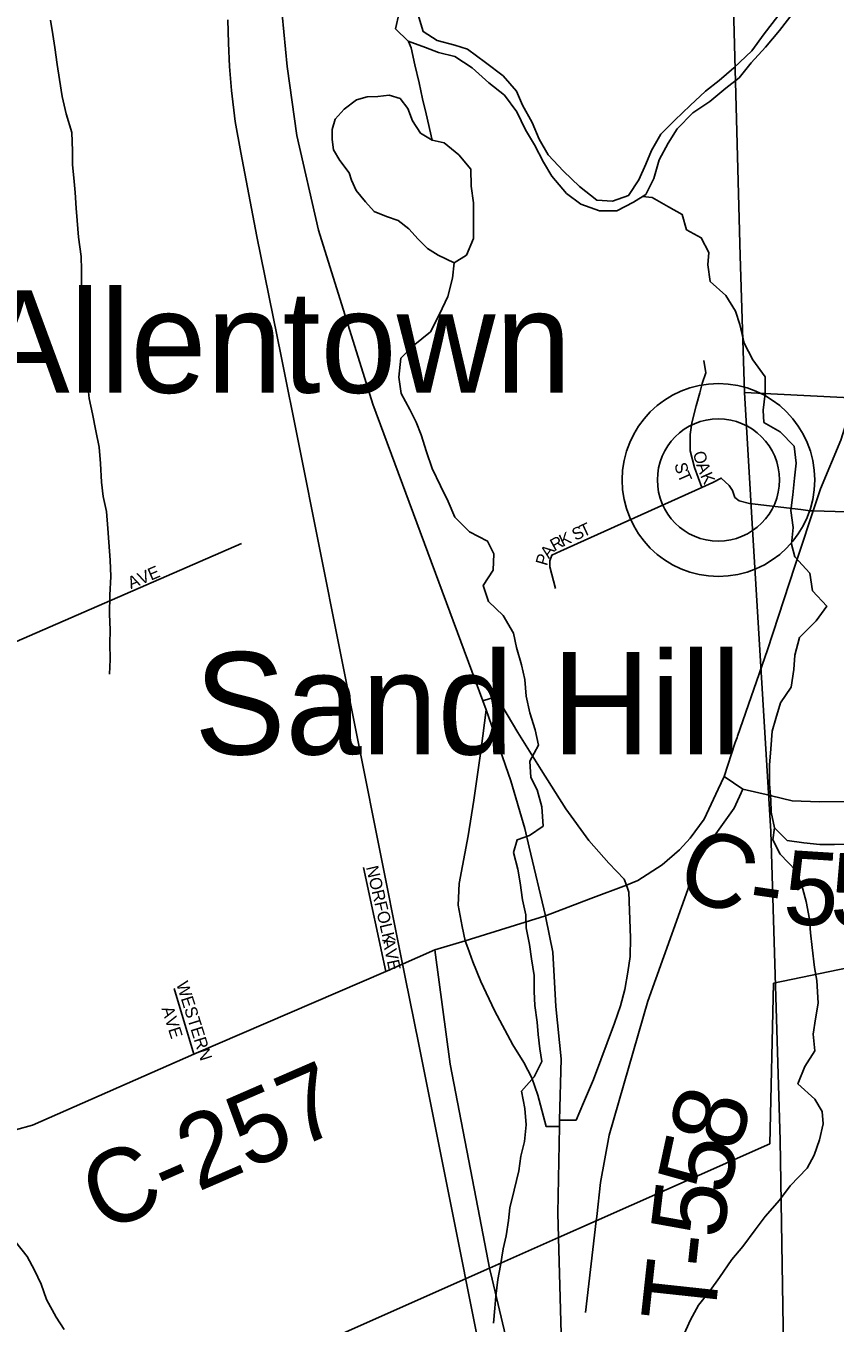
# Model space of a CAD drawing. Extents: x 1624196 to 2029251, y 146837 to 440034.
# Drawn here: x 1863402 to 1866701, y 250304 to 255591 of the extents above; entities that cross this region are included whole.
import ezdxf

# ---------------------------------------------------------------- set-up
doc = ezdxf.new("R2010")
doc.units = 0
for name, color, linetype in [('GM_X_County_Road', 7, 'Continuous'), ('GM_X_County_Road_Text', 7, 'Continuous'), ('GM_X_Interchange_Ramps', 7, 'Continuous'), ('GM_X_Minor_Lake', 7, 'Continuous'), ('GM_X_Minor_River', 7, 'Continuous'), ('GM_X_Rail_Line', 7, 'Continuous'), ('GM_X_Section', 7, 'Continuous'), ('GM_X_State_Route', 7, 'Continuous'), ('GM_X_Township', 7, 'Continuous'), ('GM_X_Township_Road', 7, 'Continuous'), ('GM_X_Township_Road_Text', 7, 'Continuous'), ('GM_X_Township_Subdivision', 7, 'Continuous'), ('GM_X_Township_Subdivision_Text', 7, 'Continuous'), ('GM_X_Unincorporated', 7, 'Continuous'), ('GM_X_Unincorporated_Location', 7, 'Continuous'), ('GM_X_Unincorporated_Text', 7, 'Continuous'), ('GM_X_US_Route', 7, 'Continuous')]:
    doc.layers.add(name, color=color, linetype=linetype)

msp = doc.modelspace()

# ---------------------------------------------------------------- linework, layer by layer
at = {"layer": 'GM_X_County_Road'}
for points in [[(1865193.3, 251862.7), (1865069.6, 251825.3), (1864868.7, 251736.8), (1864086.7, 251400.9), (1863428.9, 251110.7), (1863359.5, 251091.4), (1863284.9, 251085), (1863251.9, 251085.8), (1863225.8, 251096.5), (1863173.1, 251132.6), (1863116.5, 251177.6), (1863066.4, 251234.1), (1862399.8, 252003.8), (1862350.4, 252078.3), (1862310.9, 252140.7), (1862275.6, 252233.1), (1862160.4, 252559.1), (1861891.5, 253320.6), (1861889.7, 253325.6), (1861870.2, 253389.9), (1861867.9, 253405.1)], [(1866249.4, 252532.3), (1866325.2, 252480.5), (1866437.9, 252454.6), (1866441.7, 252453.7)], [(1866441.7, 252453.7), (1866526.7, 252432.4), (1866637.6, 252428.8), (1866776.3, 252430.6), (1866877.9, 252426.9), (1867020.3, 252421.3)]]:
    msp.add_lwpolyline(points, dxfattribs=at)
at = {"layer": 'GM_X_Interchange_Ramps'}
for points in [[(1865850.3, 252089), (1865841.8, 252114), (1865778.6, 252178.6), (1865696.7, 252271.7), (1865603.5, 252400.3), (1865502.9, 252558.7), (1865407.9, 252711.5), (1865320.3, 252858.6), (1865265, 252840.8)], [(1865577.4, 251131.8), (1865645.4, 251131.1), (1865675.2, 251202.1), (1865715.8, 251297), (1865802.4, 251526.5), (1865826.7, 251596.9), (1865843.9, 251664.5), (1865856.7, 251734.9), (1865865.9, 251798.2), (1865867.3, 251873.8), (1865859.7, 252061), (1865850.3, 252089)], [(1865193.3, 251862.7), (1865203.1, 251833.5), (1865224.4, 251777.2), (1865256.1, 251696), (1865312.4, 251578.1), (1865387.4, 251438.7), (1865432.5, 251366.8), (1865465.3, 251303.8), (1865489.5, 251233.7), (1865523.2, 251105.5), (1865577.1, 251104.9)]]:
    msp.add_lwpolyline(points, dxfattribs=at)
at = {"layer": 'GM_X_Minor_Lake'}
for points in [[(1865057.9, 255125.9), (1865010.2, 255154.3), (1864978.5, 255204.5), (1864958.8, 255254.7), (1864927.1, 255294.9), (1864883.2, 255309.2), (1864837.3, 255303.5), (1864793.3, 255301.8), (1864749.2, 255290), (1864699, 255252.3), (1864662.8, 255210.5), (1864650.5, 255168.5), (1864650.3, 255128.5), (1864656, 255086.4), (1864681.7, 255042.2), (1864719.4, 254991.9), (1864729.2, 254961.8), (1864748.9, 254919.7), (1864786.6, 254873.4), (1864822.3, 254835.1), (1864872.1, 254814.8), (1864920, 254798.5), (1864963.7, 254764.2), (1865001.4, 254721.9), (1865039.2, 254683.6), (1865082.9, 254657.3), (1865147.4, 254625.7)], [(1865147.4, 254625.7), (1865197.7, 254657.3), (1865226.2, 254725.2), (1865227.3, 254869.4), (1865217.9, 254937.5), (1865216.4, 255007.6), (1865166.9, 255066.1), (1865107.4, 255114.6), (1865057.9, 255125.9)]]:
    msp.add_lwpolyline(points, dxfattribs=at)
at = {"layer": 'GM_X_Minor_River'}
for points in [[(1863502.5, 255613.8), (1863512, 255555.7), (1863519.6, 255503.5), (1863529, 255433.4), (1863538.5, 255373.2), (1863550, 255303.1), (1863565.4, 255232.9), (1863588.8, 255156.6), (1863592.2, 255082.5), (1863591.7, 255024.4), (1863597.3, 254972.3), (1863602.8, 254912.1), (1863606.3, 254848), (1863609.9, 254798), (1863615.4, 254729.8), (1863626.7, 254651.6), (1863628.3, 254597.5), (1863627.8, 254537.5), (1863625.3, 254473.4), (1863628.7, 254399.3), (1863634.2, 254335.2), (1863639.8, 254279), (1863643.1, 254196.9), (1863652.7, 254140.8), (1863660.1, 254072.6), (1863673.6, 254010.4), (1863687, 253940.2), (1863700.5, 253874), (1863706, 253807.9), (1863709.4, 253731.8), (1863716.9, 253673.6), (1863730.4, 253611.4), (1863735.9, 253543.3), (1863739.4, 253487.2)], [(1864923.7, 255644.7), (1864909.2, 255578.7), (1864960.7, 255528.3), (1865030.5, 255503.7), (1865084.3, 255483.2), (1865150.1, 255466.7), (1865221.7, 255420.1), (1865289.2, 255359.5), (1865352.7, 255308.9), (1865404.1, 255240.4), (1865439.5, 255168), (1865475, 255105.7), (1865512.4, 255035.3), (1865546, 254979), (1865605.4, 254908.4), (1865665, 254863.9), (1865740.7, 254837.3), (1865810.7, 254836.7), (1865878.9, 254872.2), (1865929.1, 254903.9), (1865961.6, 254969.7), (1865984.2, 255045.6), (1866020.7, 255113.4), (1866057.1, 255171.2), (1866121.6, 255236.8), (1866189.9, 255282.3), (1866256.3, 255337.9), (1866310.6, 255379.5), (1866359, 255441.2), (1866417.5, 255504.8), (1866474, 255572.4), (1866530.5, 255644.1)], [(1866468.5, 255630.5), (1866411.9, 255558.9), (1866361.4, 255489.2), (1866288.9, 255419.7), (1866228.6, 255368.1), (1866172.3, 255324.5), (1866109.8, 255266.9), (1866047.4, 255207.3), (1865991, 255149.7), (1865952.5, 255083.9), (1865930.1, 255028), (1865901.6, 254964.2), (1865859.1, 254900.4), (1865793, 254876.9), (1865729.1, 254881.4), (1865659.5, 254936), (1865594.1, 254998.6), (1865530.7, 255065.2), (1865495.2, 255129.6), (1865465.8, 255197.9), (1865426.3, 255268.3), (1865402.8, 255324.5), (1865347.3, 255387), (1865275.8, 255441.7), (1865202.3, 255496.3), (1865150.5, 255512.8), (1865078.7, 255531.3), (1865021, 255567.8), (1864999.6, 255640.1)], [(1864961.9, 255527.9), (1864972.5, 255502.1), (1864988, 255431.9), (1865005.4, 255359.7), (1865018.8, 255293.5), (1865034.3, 255233.3), (1865057.9, 255125.9), (1865107.4, 255114.6), (1865166.9, 255066.1), (1865216.4, 255007.6), (1865217.9, 254937.5), (1865227.3, 254869.4), (1865226.2, 254725.2), (1865197.7, 254657.3), (1865147.4, 254625.7), (1865141, 254563.6), (1865122.4, 254487.7), (1865087.8, 254415.9), (1865051.3, 254344), (1864980.9, 254286.5), (1864930.5, 254236.9), (1864921.9, 254158.8), (1864931.4, 254092.7), (1864966.8, 254028.3), (1864992.4, 253976), (1865014, 253923.8), (1865035.4, 253855.5), (1865058.8, 253787.3), (1865092.3, 253716.9), (1865123.7, 253652.6), (1865151.2, 253588.3), (1865210.7, 253529.7), (1865284.3, 253491.1), (1865309.9, 253438.8), (1865307.4, 253372.8), (1865266.9, 253311), (1865288.4, 253244.7), (1865347.9, 253188.2), (1865389.3, 253115.8), (1865402.8, 253057.6), (1865422.2, 252987.3), (1865435.7, 252927.1), (1865441.2, 252859), (1865456.6, 252790.8), (1865478.1, 252722.5), (1865491.6, 252660.3), (1865457.1, 252594.5), (1865460.6, 252528.4), (1865486.1, 252478.1), (1865505.6, 252407.9), (1865510.9, 252329.7), (1865454.7, 252292.1), (1865404.6, 252274.5), (1865390.2, 252222.5), (1865407.6, 252154.3), (1865417.2, 252098.1), (1865426.6, 252030), (1865440.1, 251967.8), (1865441.7, 251915.7), (1865455.1, 251847.5), (1865462.7, 251789.3), (1865474.1, 251721.1), (1865473.6, 251655.1), (1865477.1, 251598.9), (1865486.6, 251530.8), (1865490.2, 251480.7), (1865497.7, 251422.5), (1865505.3, 251370.4), (1865474.8, 251308.5), (1865422.4, 251248.9), (1865435.8, 251178.7), (1865441.3, 251112.5), (1865434.7, 251044.5), (1865420.3, 250984.5), (1865411.8, 250924.5), (1865393.2, 250846.5), (1865374.6, 250774.6), (1865370.2, 250722.5), (1865359.7, 250660.5), (1865347.3, 250606.5), (1865336.8, 250538.5), (1865326.3, 250482.5), (1865317.8, 250414.5), (1865313.4, 250364.5), (1865308.9, 250304.4)], [(1865916, 254895.6), (1865955, 254891.6), (1866022.6, 254853.1), (1866078.3, 254822.6), (1866095.8, 254760.4), (1866155.5, 254727.9), (1866187, 254667.5), (1866182.6, 254617.5), (1866192.1, 254549.4), (1866255.6, 254492.8), (1866295.1, 254428.4), (1866312.6, 254374.2), (1866330, 254297.9), (1866365.4, 254229.6), (1866416.8, 254161.1), (1866416.3, 254093), (1866407.8, 254025), (1866411.4, 253974.9), (1866477, 253936.3), (1866534.5, 253877.8), (1866542, 253809.6), (1866535.5, 253747.6), (1866528.9, 253679.6), (1866520.4, 253615.6), (1866529.9, 253547.4), (1866523.4, 253479.4), (1866536.9, 253427.2), (1866598.4, 253360.6), (1866609.8, 253288.4), (1866667.2, 253225.9), (1866624.8, 253166.1), (1866556.3, 253098.6), (1866537.7, 253026.6), (1866533.3, 252968.6), (1866522.7, 252896.6), (1866478.2, 252832.8), (1866459.7, 252768.9), (1866445.3, 252716.9), (1866438.8, 252644.9), (1866434.3, 252578.8), (1866433.6, 252502.7), (1866439.1, 252436.6), (1866440.7, 252386.5), (1866454.2, 252322.3), (1866505.8, 252271.8), (1866573.6, 252261.3), (1866639.5, 252254.8), (1866699.5, 252254.3), (1866765.4, 252255.8)], [(1863739.4, 253487.2), (1863744.8, 253413.1), (1863748.3, 253346.9), (1863743.7, 253270.9), (1863743.1, 253194.8), (1863744.5, 253128.7), (1863744.1, 253074.6), (1863745.6, 253008.5), (1863743.1, 252948.4)], [(1866454.2, 252322.3), (1866447.8, 252274.3), (1866477.3, 252216), (1866542.7, 252147.4), (1866570.1, 252073.1), (1866583.7, 252022.9), (1866597.1, 251950.7), (1866600.7, 251894.6), (1866608.2, 251834.4), (1866617.6, 251754.2), (1866627.1, 251700.1), (1866632.4, 251607.9), (1866621.9, 251543.9), (1866611.4, 251481.9), (1866618.8, 251413.7), (1866578.4, 251350), (1866549.8, 251280.1), (1866619.3, 251217.5), (1866648.8, 251167.2), (1866652.4, 251117.1), (1866637.9, 251051.1), (1866615.5, 250989.2), (1866587, 250935.3), (1866518.5, 250863.8), (1866474.1, 250806), (1866415.6, 250738.4), (1866375.2, 250684.6), (1866324.7, 250616.9), (1866280.3, 250563.2), (1866229.7, 250489.5), (1866191.3, 250437.7), (1866144.9, 250378), (1866112.4, 250318.1), (1866079.9, 250248.3)], [(1863360.9, 250634.2), (1863406.4, 250575.7), (1863436, 250519.4), (1863463.5, 250463.1), (1863485, 250400.8), (1863524.4, 250328.4), (1863557.9, 250278.1)]]:
    msp.add_lwpolyline(points, dxfattribs=at)
at = {"layer": 'GM_X_Rail_Line'}
msp.add_lwpolyline([(1864225.2, 255615.2), (1864227.6, 255520.9), (1864232.4, 255425.8), (1864239.7, 255328.3), (1864255, 255201.7), (1864277.6, 255075.2), (1864342.9, 254732.6), (1864442, 254245), (1864513.9, 253886.7), (1864928.8, 251807.6), (1865003.8, 251440.1), (1865105.3, 250930.7), (1865274.6, 250086.8), (1865451.1, 249207.5), (1865659.1, 248170.9), (1865783.2, 247548.7), (1865901.7, 246959.5), (1866042.7, 246254.3)], dxfattribs=at)
at = {"layer": 'GM_X_Section'}
for points in [[(1871606.9, 259505.4), (1871337.4, 253843.7), (1866331.8, 254096.9), (1866313.6, 254654.5), (1866278.3, 255971.5), (1866237.4, 257382.6), (1866193.8, 258839.6), (1866171.2, 259752)], [(1866331.8, 254096.9), (1871337.4, 253843.7), (1871311.7, 253337.8), (1871279.5, 252691.8), (1871251.4, 252067.9), (1871230.1, 251695.9), (1870151.3, 251240.3), (1866498.7, 249697.9), (1866477.4, 251049.4), (1866438.9, 252307.4), (1866365.1, 253540.6)]]:
    msp.add_lwpolyline(points, close=True, dxfattribs=at)
at = {"layer": 'GM_X_State_Route'}
for points in [[(1866553.6, 253438), (1866611.7, 253614.8), (1866641.3, 253705), (1866725.3, 253903.3), (1866817.6, 254197.2), (1866839.2, 254265.8), (1866955.1, 254612.3), (1867019.4, 254793.8), (1867065, 254922.7), (1867141, 255171.1), (1867192.9, 255385.4), (1867248.8, 255625.7), (1867266.6, 255748.2), (1867316.7, 256094.4), (1867331.3, 256209.5)], [(1866294.5, 252670), (1866301.6, 252691.5), (1866303.2, 252696.3), (1866425.5, 253048.1), (1866537.4, 253388.6), (1866553.6, 253438)], [(1865278.8, 252803.6), (1865258, 252644.8), (1865227.7, 252435), (1865204.9, 252290), (1865167.9, 252095.8), (1865164.2, 252007), (1865181.1, 251920.1), (1865193.3, 251862.7)], [(1866224.9, 252480), (1866249.4, 252532.3), (1866294.5, 252670)], [(1865520.1, 251964.4), (1865705.9, 252034.8), (1865850.3, 252089), (1865896.3, 252108.8), (1865996.1, 252171.6), (1866066.3, 252232.7), (1866110.7, 252280.8), (1866168.1, 252358.5), (1866224.9, 252480)], [(1865193.3, 251862.7), (1865520.1, 251964.4)]]:
    msp.add_lwpolyline(points, dxfattribs=at)
at = {"layer": 'GM_X_Township'}
for points in [[(1863301, 246528.5), (1862714.9, 247271.4), (1862100.9, 248148.6), (1861509.1, 248848.3), (1862580.3, 249323.9), (1865292.3, 250528.1), (1865572.9, 250652.7), (1865727.1, 250721.2), (1866434.9, 251035.5), (1866450.4, 251689.5), (1866942.6, 251791.9), (1868357, 252095.4), (1869903.4, 252424.5), (1870787.7, 252612.8), (1870777.5, 251495.4), (1875312.3, 253466.4), (1878340.6, 254803.1), (1879987.6, 255523.4), (1880436.8, 255719.9), (1880982.4, 255958.6), (1882319.5, 256543.4), (1883080.6, 256876.3)], [(1875312.3, 253466.4), (1870777.5, 251495.4), (1870787.7, 252612.8), (1869903.4, 252424.5), (1868357, 252095.4), (1866942.6, 251791.9), (1866450.4, 251689.5), (1866434.9, 251035.5), (1865727.1, 250721.2), (1865572.9, 250652.7), (1865292.3, 250528.1), (1862580.3, 249323.9), (1861509.1, 248848.3), (1861355.8, 249029.6), (1861118.4, 249480.7), (1860989.6, 249941.6), (1860746, 251186.1), (1860722.2, 252254.2), (1860738.2, 252976.8), (1861176.3, 255403.9), (1861269.5, 255936.8)]]:
    msp.add_lwpolyline(points, dxfattribs=at)
at = {"layer": 'GM_X_Township_Road'}
for points in [[(1865729.1, 250738.7), (1865745.2, 250877.6), (1865780.2, 251070.4), (1865937.3, 251615.7), (1866140.3, 252180.9), (1866201.3, 252278.9), (1866290, 252402.8), (1866325.2, 252480.5)], [(1865259.6, 250697.7), (1865132.1, 251359.5), (1865069.6, 251825.3)], [(1865683.9, 250347.4), (1865727.1, 250721.2), (1865729.1, 250738.7)], [(1867754.5, 238418), (1867606.5, 239131.1), (1866702, 243591.4), (1866247.1, 245936.9), (1865460.6, 249817.3), (1865302.4, 250483.4), (1865292.3, 250528.1), (1865259.6, 250697.7)]]:
    msp.add_lwpolyline(points, dxfattribs=at)
at = {"layer": 'GM_X_Township_Subdivision'}
for points in [[(1866157.6, 253709.8), (1866127.6, 253791), (1866110.1, 253859.2), (1866110.6, 253925.3), (1866116.9, 253973.3), (1866135.3, 254043.3), (1866149.6, 254095.3), (1866159.9, 254133.3), (1866174.2, 254177.2), (1866166.5, 254227.3)], [(1865561.3, 253297.9), (1865537.9, 253386.7), (1865538, 253410.8), (1865546.2, 253434.7), (1865582.2, 253450.5), (1866157.6, 253709.8), (1866203.1, 253730.3), (1866237.1, 253748.1), (1866268.9, 253717.8), (1866282.7, 253697.7), (1866292.5, 253669.6), (1866310.4, 253655.4), (1866352.3, 253645.1), (1866562.3, 253619.7)], [(1866562.3, 253619.7), (1866599.6, 253615.2), (1866611.7, 253614.8), (1867060.9, 253601.1)], [(1862160.4, 252559.1), (1864280.7, 253482.2)], [(1864868.7, 251736.8), (1864777.9, 252161)], [(1864086.7, 251400.9), (1864006.7, 251667.6)]]:
    msp.add_lwpolyline(points, dxfattribs=at)
at = {"layer": 'GM_X_Unincorporated'}
for radius in [392.8, 249]:
    msp.add_circle((1866225.6, 253740.4), radius, dxfattribs=at)
at = {"layer": 'GM_X_Unincorporated_Location'}
msp.add_line((1866225.6, 253740.4), (1866225.6, 253740.4), dxfattribs=at)
at = {"layer": 'GM_X_US_Route'}
for points in [[(1864746.6, 256909.7), (1864715.3, 256846.3), (1864609.8, 256606.5), (1864550.5, 256398.4), (1864468.4, 256052.2), (1864440.3, 255709.7), (1864466.5, 255425), (1864506.9, 255144.3), (1864594.6, 254759.1), (1864815.8, 254049.9), (1865265, 252840.8), (1865278.8, 252803.6)], [(1865278.8, 252803.6), (1865378.9, 252514.4), (1865436.4, 252320.6), (1865453.9, 252243.5), (1865520.1, 251964.4), (1865521.9, 251955.5)], [(1865521.9, 251955.5), (1865549.9, 251816.4), (1865562, 251594), (1865584, 251381.6), (1865577.4, 251131.8), (1865577.1, 251104.9), (1865570.1, 250752.6), (1865572.9, 250652.7), (1865585.3, 250211.7), (1865607.2, 249867.2), (1865751.4, 249001.9), (1865848.9, 248500.8)]]:
    msp.add_lwpolyline(points, dxfattribs=at)

# ---------------------------------------------------------------- texts
at = {"layer": 'GM_X_County_Road_Text'}
for s, rotation, p in [('C', 338.3511, (1866036.7, 252063.9)), ('5', 356.3635, (1866485, 251933.7)), ('5', 358.3282, (1866679.1, 251921.6)), ('-', 351.7427, (1866337.8, 251954)), ('C-257', 23.4881, (1863714.4, 250669.6))]:
    msp.add_text(s, height=300, rotation=rotation, dxfattribs=at).set_placement(p)
at = {"layer": 'GM_X_Township_Road_Text'}
for s, rotation, p in [('8', 73.8251, (1866304.1, 250994.3)), ('5', 77.7664, (1866266.3, 250819)), ('5', 83.1038, (1866245.4, 250642.8)), ('-', 83.7115, (1866232, 250521.2)), ('T', 83.8382, (1866207.9, 250298.2))]:
    msp.add_text(s, height=300, rotation=rotation, dxfattribs=at).set_placement(p)
at = {"layer": 'GM_X_Township_Subdivision_Text'}
for s, rotation, p in [('O', 283.75, (1866121.6, 253851.6)), ('S', 283.6254, (1866045.8, 253805.3)), ('A', 291.0086, (1866134.1, 253802.3)), ('T', 293.8771, (1866057.2, 253761.9)), ('K', 293.9391, (1866150.9, 253758.6)), ('S', 24.9538, (1865642.3, 253491.8)), ('T', 24.9619, (1865674.3, 253506.7)), ('R', 28.814, (1865556.5, 253449)), ('K', 24.9423, (1865590.4, 253467.7)), ('P', 73.6043, (1865526.4, 253388)), ('A', 52.9072, (1865534.2, 253417.5)), ('AVE', 22.9337, (1863829.5, 253295.1)), ('NORFOLK', 283.1899, (1864788.3, 252162.2)), ('AVE', 282.095, (1864854.4, 251867.2)), ('WESTERN', 287.613, (1864013.7, 251687.7)), ('AVE', 287.8169, (1863953.8, 251586.6))]:
    msp.add_text(s, height=50, rotation=rotation, dxfattribs=at).set_placement(p)
at = {"layer": 'GM_X_Unincorporated_Text'}
for s, p in [('Allentown', (1863208.4, 254095.8)), ('Sand Hill', (1864088.4, 252621.8))]:
    msp.add_text(s, height=417, rotation=0, dxfattribs=at).set_placement(p)

doc.saveas('drawing.dxf')
